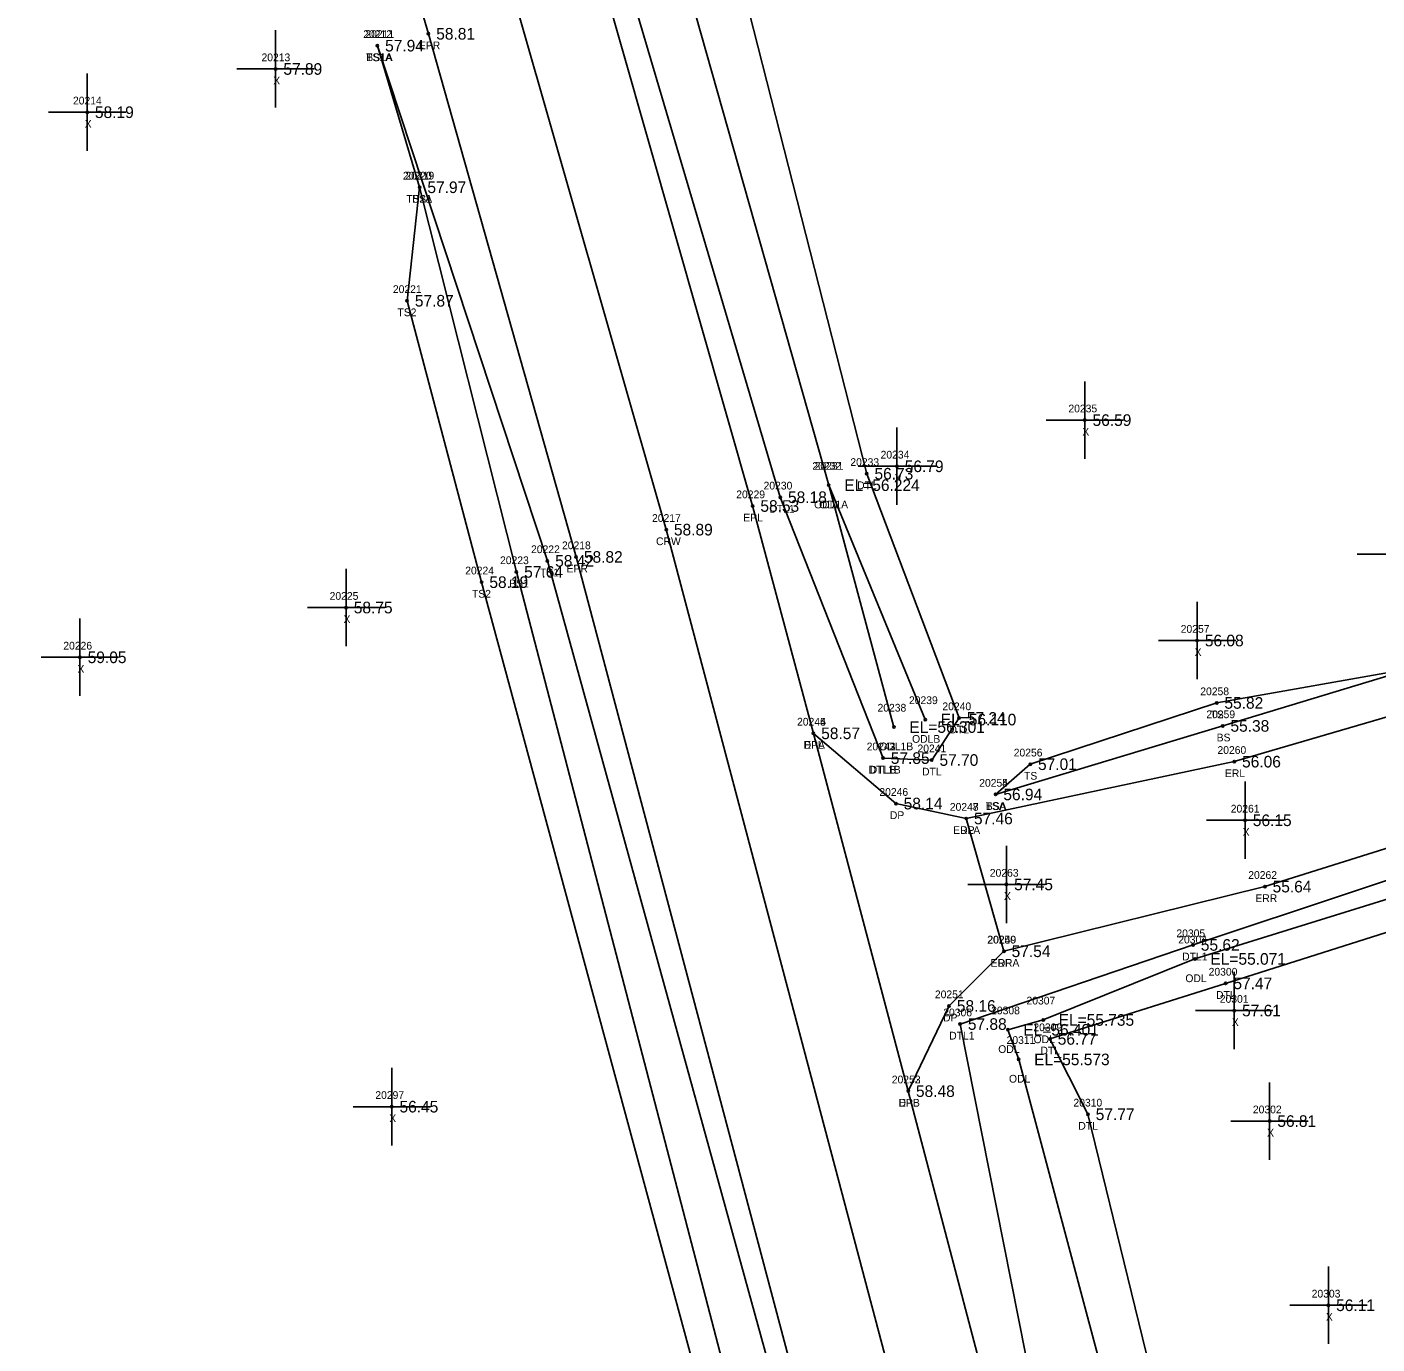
# Model space of a CAD drawing. Extents: x 2396547 to 2397655, y 770185 to 772649.
# Drawn here: x 2396876.7 to 2397051.2, y 771642.4 to 771812.6 of the extents above; entities that cross this region are included whole.
import ezdxf

# ---------------------------------------------------------------- set-up
doc = ezdxf.new("R2010")
doc.units = 0
for name, color, linetype in [('RD_DTM_BkLn1', 7, 'Continuous'), ('RD_DTM_BkLn2', 7, 'Continuous'), ('RD_DTM_BkLn_txCode', 7, 'Continuous'), ('RD_EX_Driveway', 7, 'Continuous'), ('RD_EX_Driveway_txCode', 7, 'Continuous'), ('RD_EX_H2O', 7, 'Continuous'), ('RD_EX_H2O_txCode', 7, 'Continuous'), ('RD_EX_Misc', 7, 'Continuous'), ('RD_EX_Misc_txCode', 7, 'Continuous'), ('RD_EX_Road', 7, 'Continuous'), ('RD_EX_Road_txCode', 7, 'Continuous'), ('RD_EX_TX_Driveway_ELEV', 7, 'Continuous'), ('RD_EX_TX_H2O_ELEV', 7, 'Continuous'), ('RD_EX_TX_Misc_ELEV', 7, 'Continuous'), ('RD_EX_TX_Road_ELEV', 7, 'Continuous'), ('RD_HC_Survey_ELEV', 7, 'Continuous'), ('RD_HC_Survey_txCode', 7, 'Continuous'), ('RD_SMD_Locator', 7, 'Continuous')]:
    doc.layers.add(name, color=color, linetype=linetype)

msp = doc.modelspace()

# ---------------------------------------------------------------- linework, layer by layer
at = {"layer": 'RD_DTM_BkLn1'}
msp.add_lwpolyline([(2396669.86, 772614.94), (2396704.28, 772521.49), (2396739.29, 772426.89), (2396775.36, 772328.69), (2396800.21, 772259.35), (2396825.58, 772185.8), (2396852.46, 772104.52), (2396872.48, 772041.55), (2396897.57, 771959.72), (2396918.76, 771888.68), (2396939.09, 771818.34), (2396959.29, 771747.62), (2396993.72, 771617.68), (2397022.56, 771506.67), (2397049.1, 771404.69)], dxfattribs=at)
at = {"layer": 'RD_DTM_BkLn2'}
for points in [[(2396921.95, 771810.18), (2396943.94, 771743.58), (2396982.88, 771602.26), (2397008.66, 771503.58), (2397035.9, 771402.4)], [(2396921.95, 771810.18), (2396927.42, 771791.88), (2396939.93, 771742.16), (2396976.22, 771602.97), (2396999, 771501.35), (2397026.41, 771393.39)], [(2396927.42, 771791.88), (2396925.8, 771777.21), (2396935.43, 771740.83), (2396970.29, 771612.06), (2396976.22, 771602.97)], [(2397001.88, 771713.39), (2397031.24, 771722.25), (2397055.87, 771729.7)], [(2397001.88, 771713.39), (2397006.36, 771717.3), (2397030.46, 771725.22), (2397055.87, 771729.7)]]:
    msp.add_lwpolyline(points, dxfattribs=at)
at = {"layer": 'RD_EX_Driveway'}
msp.add_lwpolyline([(2396978.33, 771721.29), (2396988.99, 771712.21), (2396998.08, 771710.28), (2397002.95, 771693.12), (2396995.87, 771686.05), (2396990.58, 771675.04)], dxfattribs=at)
at = {"layer": 'RD_EX_H2O'}
msp.add_line((2396980.31, 771753.37), (2396988.73, 771722.1), dxfattribs=at)
for points in [[(2396946.35, 771904.67), (2396938.36, 771904.07), (2396931.6, 771898.52), (2396953.06, 771822.86), (2396974.04, 771751.81), (2396987.33, 771718.09)], [(2396946.35, 771904.67), (2396967.2, 771825.55), (2396985.22, 771754.85), (2396997.16, 771723.28), (2396993.62, 771717.84), (2396987.33, 771718.09)], [(2396941.93, 771898.99), (2396960.38, 771823.86), (2396980.31, 771753.37), (2396992.79, 771723.07)], [(2397132.06, 771727.73), (2397069.65, 771707.99), (2397027.41, 771693.94), (2396997.29, 771683.71), (2397009.52, 771621.94), (2397039.8, 771510.33), (2397059.22, 771428.3), (2397068.26, 771415.82), (2397065.8, 771409.74)], [(2397133.23, 771725), (2397070.25, 771705.35), (2397027.65, 771692.13), (2397008.03, 771684.24), (2397003.46, 771682.97), (2397004.86, 771679.14), (2397019.55, 771624.25), (2397050.23, 771512.98), (2397072.95, 771431.23), (2397072.81, 771420.44), (2397072.44, 771413.81)], [(2397133.83, 771721.66), (2397071.25, 771701.52), (2397031.62, 771688.97), (2397008.91, 771681.79), (2397013.82, 771672.05), (2397025.11, 771625.88), (2397054.64, 771514.68), (2397075.97, 771429.94), (2397072.44, 771413.81)]]:
    msp.add_lwpolyline(points, dxfattribs=at)
at = {"layer": 'RD_EX_Misc'}
for p, q in [((2396908.8, 771802.17), (2396908.8, 771812.17)), ((2396884.44, 771796.58), (2396884.44, 771806.58)), ((2396903.8, 771807.17), (2396913.8, 771807.17)), ((2396879.44, 771801.58), (2396889.44, 771801.58)), ((2397013.41, 771756.78), (2397013.41, 771766.78)), ((2396989.13, 771750.81), (2396989.13, 771760.81)), ((2397008.41, 771761.78), (2397018.41, 771761.78)), ((2396984.13, 771755.81), (2396994.13, 771755.81)), ((2397048.64, 771744.47), (2397058.64, 771744.47)), ((2396917.9, 771732.55), (2396917.9, 771742.55)), ((2397027.93, 771728.29), (2397027.93, 771738.29)), ((2396883.5, 771726.12), (2396883.5, 771736.12)), ((2396912.9, 771737.55), (2396922.9, 771737.55)), ((2397022.93, 771733.29), (2397032.93, 771733.29)), ((2396878.5, 771731.12), (2396888.5, 771731.12)), ((2397034.13, 771705.05), (2397034.13, 771715.05)), ((2397029.13, 771710.05), (2397039.13, 771710.05)), ((2397003.27, 771696.76), (2397003.27, 771706.76)), ((2396998.27, 771701.76), (2397008.27, 771701.76)), ((2397032.74, 771680.46), (2397032.74, 771690.46)), ((2397027.74, 771685.46), (2397037.74, 771685.46)), ((2396923.81, 771668.03), (2396923.81, 771678.03)), ((2397037.3, 771666.17), (2397037.3, 771676.17)), ((2396918.81, 771673.03), (2396928.81, 771673.03)), ((2397032.3, 771671.17), (2397042.3, 771671.17)), ((2397044.9, 771642.36), (2397044.9, 771652.36)), ((2397039.9, 771647.36), (2397049.9, 771647.36))]:
    msp.add_line(p, q, dxfattribs=at)
at = {"layer": 'RD_EX_Road'}
for points in [[(2396680.92, 772617.84), (2396715.6, 772525.73), (2396750.68, 772430.62), (2396786.3, 772332.21), (2396811.38, 772263.31), (2396839.69, 772181.74), (2396863.75, 772109.83), (2396883.63, 772046.56), (2396889.54, 772027.11), (2396896.25, 772004.37), (2396904.34, 771978.33), (2396908.24, 771964.89), (2396921.74, 771919.68), (2396927.03, 771902.11), (2396950.2, 771821.74), (2396970.47, 771750.68), (2396978.33, 771721.29), (2396990.58, 771675.04), (2397004.94, 771620.49), (2397034.26, 771508.8), (2397061.11, 771410.49), (2397060.64, 771407.04), (2397062.07, 771407.67)], [(2396658.78, 772611.07), (2396693.37, 772516.9), (2396729.65, 772418.78), (2396760.7, 772333.11), (2396788.58, 772254.87), (2396814.65, 772181.57), (2396841.1, 772100.86), (2396861.19, 772037.76), (2396886.09, 771955.71), (2396907.15, 771884.49), (2396928.56, 771811.72), (2396947.65, 771744.09), (2396985.17, 771602.64), (2397011.11, 771504.04), (2397037.95, 771404.25), (2397039, 771401.22)], [(2396998.08, 771710.28), (2397032.74, 771717.63), (2397062.52, 771726.35), (2397126.64, 771745.15)], [(2397002.95, 771693.12), (2397036.69, 771701.48), (2397068.39, 771711.44), (2397131.44, 771730.05)]]:
    msp.add_lwpolyline(points, dxfattribs=at)
at = {"layer": 'RD_SMD_Locator'}
for centre in [(2396928.56, 771811.72), (2396921.95, 771810.18), (2396921.95, 771810.18), (2396908.8, 771807.17), (2396884.44, 771801.58), (2396927.42, 771791.88), (2396927.42, 771791.88), (2396925.8, 771777.21), (2397013.41, 771761.78), (2396989.13, 771755.81), (2396980.31, 771753.37), (2396980.31, 771753.37), (2396985.22, 771754.85), (2396974.04, 771751.81), (2396970.47, 771750.68), (2396959.29, 771747.62), (2396943.94, 771743.58), (2396947.65, 771744.09), (2396939.93, 771742.16), (2396935.43, 771740.83), (2396917.9, 771737.55), (2397027.93, 771733.29), (2396883.5, 771731.12), (2397030.46, 771725.22), (2396988.73, 771722.1), (2396992.79, 771723.07), (2396997.16, 771723.28), (2397031.24, 771722.25), (2396978.33, 771721.29), (2396978.33, 771721.29), (2396987.33, 771718.09), (2396987.33, 771718.09), (2396993.62, 771717.84), (2397006.36, 771717.3), (2397032.74, 771717.63), (2397001.88, 771713.39), (2397001.88, 771713.39), (2396988.99, 771712.21), (2396998.08, 771710.28), (2396998.08, 771710.28), (2397034.13, 771710.05), (2397003.27, 771701.76), (2397036.69, 771701.48), (2397002.95, 771693.12), (2397002.95, 771693.12), (2397027.41, 771693.94), (2397027.65, 771692.13), (2397031.62, 771688.97), (2396995.87, 771686.05), (2397032.74, 771685.46), (2396997.29, 771683.71), (2397008.03, 771684.24), (2397003.46, 771682.97), (2397008.91, 771681.79), (2397004.86, 771679.14), (2396990.58, 771675.04), (2396990.58, 771675.04), (2396923.81, 771673.03), (2397013.82, 771672.05), (2397037.3, 771671.17), (2397044.9, 771647.36)]:
    msp.add_circle(centre, 0.15, dxfattribs=at)

# ---------------------------------------------------------------- texts
at = {"layer": 'RD_DTM_BkLn_txCode'}
for s, p in [('20212', (2396920.12, 771811.18)), ('20211', (2396920.4, 771811.18)), ('TS1A', (2396920.5, 771808.18)), ('BS1A', (2396920.52, 771808.18)), ('20220', (2396925.26, 771792.88)), ('20219', (2396925.58, 771792.88)), ('TS2A', (2396925.69, 771789.88)), ('BS1', (2396926.47, 771789.88)), ('20221', (2396923.96, 771778.21)), ('TS2', (2396924.55, 771775.21)), ('20222', (2396941.82, 771744.58)), ('20223', (2396937.81, 771743.16)), ('20224', (2396933.31, 771741.83)), ('TS1', (2396942.98, 771741.58)), ('TS2', (2396934.18, 771738.83)), ('BS1', (2396938.99, 771740.16)), ('20258', (2397028.34, 771726.22)), ('20259', (2397029.12, 771723.25)), ('TS', (2397029.66, 771723.22)), ('BS', (2397030.46, 771720.25)), ('20256', (2397004.22, 771718.3)), ('20254', (2396999.76, 771714.39)), ('20255', (2396999.76, 771714.39)), ('TS', (2397005.56, 771715.3)), ('TSA', (2397000.59, 771711.39)), ('BSA', (2397000.61, 771711.39))]:
    msp.add_text(s, height=1, dxfattribs=at).set_placement(p)
at = {"layer": 'RD_EX_Driveway_txCode'}
for s, p in [('20245', (2396976.21, 771722.29)), ('DPA', (2396977.06, 771719.29)), ('20246', (2396986.85, 771713.21)), ('20247', (2396995.96, 771711.28)), ('DP', (2396988.21, 771710.21)), ('DP', (2396997.3, 771708.28)), ('20249', (2397000.83, 771694.12)), ('DP', (2397002.17, 771691.12)), ('20251', (2396994.03, 771687.05)), ('DP', (2396995.09, 771684.05)), ('20252', (2396988.46, 771676.04)), ('DPB', (2396989.33, 771673.04))]:
    msp.add_text(s, height=1, dxfattribs=at).set_placement(p)
at = {"layer": 'RD_EX_H2O_txCode'}
for s, p in [('20232', (2396978.19, 771755.37)), ('20231', (2396978.48, 771755.37)), ('20233', (2396983.1, 771755.85)), ('20230', (2396971.88, 771752.81)), ('DTL', (2396983.98, 771752.85)), ('DTL1', (2396972.63, 771749.81)), ('ODL1A', (2396978.42, 771750.37)), ('ODL', (2396979.07, 771750.37)), ('20239', (2396990.68, 771725.07)), ('20238', (2396986.61, 771724.1)), ('20240', (2396995, 771724.28)), ('DTL', (2396995.91, 771721.28)), ('ODLB', (2396991.08, 771720.07)), ('20242', (2396985.21, 771719.09)), ('20243', (2396985.21, 771719.09)), ('ODL1B', (2396986.84, 771719.1)), ('20241', (2396991.78, 771718.84)), ('DTL1B', (2396985.45, 771716.09)), ('DTLB', (2396985.61, 771716.09)), ('DTL', (2396992.37, 771715.84)), ('20305', (2397025.25, 771694.94)), ('20304', (2397025.49, 771694.13)), ('DTL1', (2397026, 771691.94)), ('20300', (2397029.42, 771689.97)), ('ODL', (2397026.41, 771689.13)), ('20307', (2397005.87, 771686.24)), ('DTL', (2397030.38, 771686.97)), ('20306', (2396995.11, 771684.71)), ('20308', (2397001.3, 771684.97)), ('20309', (2397006.76, 771682.79)), ('DTL1', (2396995.88, 771681.71)), ('20311', (2397003.3, 771681.14)), ('ODL', (2397006.79, 771681.24)), ('ODL', (2397002.22, 771679.97)), ('DTL', (2397007.67, 771679.79)), ('ODL', (2397003.61, 771676.14)), ('20310', (2397011.94, 771673.05)), ('DTL', (2397012.57, 771670.05))]:
    msp.add_text(s, height=1, dxfattribs=at).set_placement(p)
at = {"layer": 'RD_EX_Misc_txCode'}
for s, p in [('20213', (2396906.97, 771808.17)), ('X', (2396908.49, 771805.17)), ('20214', (2396882.6, 771802.58)), ('X', (2396884.12, 771799.58)), ('20235', (2397011.29, 771762.78)), ('X', (2397013.09, 771759.78)), ('20234', (2396987.01, 771756.81)), ('X', (2396988.81, 771753.81)), ('20225', (2396915.78, 771738.55)), ('X', (2396917.58, 771735.55)), ('20257', (2397025.81, 771734.29)), ('20226', (2396881.35, 771732.12)), ('X', (2397027.61, 771731.29)), ('X', (2396883.18, 771729.12)), ('20261', (2397032.28, 771711.05)), ('X', (2397033.82, 771708.05)), ('20263', (2397001.13, 771702.76)), ('X', (2397002.96, 771699.76)), ('20301', (2397030.86, 771686.46)), ('X', (2397032.42, 771683.46)), ('20297', (2396921.69, 771674.03)), ('X', (2396923.49, 771671.03)), ('20302', (2397035.14, 771672.17)), ('X', (2397036.98, 771669.17)), ('20303', (2397042.74, 771648.36)), ('X', (2397044.58, 771645.36))]:
    msp.add_text(s, height=1, dxfattribs=at).set_placement(p)
at = {"layer": 'RD_EX_Road_txCode'}
for s, p in [('EPR', (2396927.33, 771809.72)), ('20229', (2396968.35, 771751.68)), ('EPL', (2396969.26, 771748.68)), ('20218', (2396945.82, 771745.09)), ('EPR', (2396946.42, 771742.09)), ('20244', (2396976.21, 771722.29)), ('EPL', (2396977.13, 771719.29)), ('20260', (2397030.56, 771718.63)), ('ERL', (2397031.53, 771715.63)), ('20248', (2396995.96, 771711.28)), ('ERLA', (2396996.39, 771708.28)), ('20262', (2397034.54, 771702.48)), ('ERR', (2397035.46, 771699.48)), ('20250', (2397000.79, 771694.12)), ('ERRA', (2397001.23, 771691.12)), ('20253', (2396988.46, 771676.04)), ('EPL', (2396989.38, 771673.04))]:
    msp.add_text(s, height=1, dxfattribs=at).set_placement(p)
at = {"layer": 'RD_EX_TX_Driveway_ELEV'}
for s, p in [('58.57', (2396979.33, 771720.54)), ('58.14', (2396989.99, 771711.46)), ('57.46', (2396999.08, 771709.53)), ('57.54', (2397003.95, 771692.37)), ('58.16', (2396996.87, 771685.3)), ('58.48', (2396991.58, 771674.29))]:
    msp.add_text(s, height=1.5, dxfattribs=at).set_placement(p)
at = {"layer": 'RD_EX_TX_H2O_ELEV'}
for s, p in [('56.73', (2396986.22, 771754.1)), ('EL=56.224', (2396982.31, 771752.62)), ('EL=56.224', (2396982.31, 771752.62)), ('58.18', (2396975.04, 771751.06)), ('57.24', (2396998.16, 771722.53)), ('EL=56.301', (2396990.73, 771721.35)), ('EL=56.110', (2396994.79, 771722.32)), ('57.85', (2396988.33, 771717.34)), ('57.85', (2396988.33, 771717.34)), ('57.70', (2396994.62, 771717.09)), ('55.62', (2397028.41, 771693.19)), ('EL=55.071', (2397029.65, 771691.38)), ('57.47', (2397032.62, 771688.22)), ('57.88', (2396998.29, 771682.96)), ('EL=56.401', (2397005.46, 771682.22)), ('EL=55.735', (2397010.03, 771683.49)), ('56.77', (2397009.91, 771681.04)), ('EL=55.573', (2397006.86, 771678.39)), ('57.77', (2397014.82, 771671.3))]:
    msp.add_text(s, height=1.5, dxfattribs=at).set_placement(p)
at = {"layer": 'RD_EX_TX_Misc_ELEV'}
for s, p in [('57.94', (2396922.95, 771809.43)), ('57.94', (2396922.95, 771809.43)), ('57.89', (2396909.8, 771806.42)), ('58.19', (2396885.44, 771800.83)), ('57.97', (2396928.42, 771791.13)), ('57.97', (2396928.42, 771791.13)), ('57.87', (2396926.8, 771776.46)), ('56.59', (2397014.41, 771761.03)), ('56.79', (2396990.13, 771755.06)), ('58.42', (2396944.94, 771742.83)), ('58.19', (2396936.43, 771740.08)), ('57.64', (2396940.93, 771741.41)), ('58.75', (2396918.9, 771736.8)), ('56.08', (2397028.93, 771732.54)), ('59.05', (2396884.5, 771730.37)), ('55.82', (2397031.46, 771724.47)), ('55.38', (2397032.24, 771721.5)), ('57.01', (2397007.36, 771716.55)), ('56.94', (2397002.88, 771712.64)), ('56.94', (2397002.88, 771712.64)), ('56.15', (2397035.13, 771709.3)), ('57.45', (2397004.27, 771701.01)), ('57.61', (2397033.74, 771684.71)), ('56.45', (2396924.81, 771672.28)), ('56.81', (2397038.3, 771670.42)), ('56.11', (2397045.9, 771646.61))]:
    msp.add_text(s, height=1.5, dxfattribs=at).set_placement(p)
at = {"layer": 'RD_EX_TX_Road_ELEV'}
for s, p in [('58.81', (2396929.56, 771810.97)), ('58.53', (2396971.47, 771749.93)), ('58.82', (2396948.65, 771743.34)), ('58.57', (2396979.33, 771720.54)), ('56.06', (2397033.74, 771716.88)), ('57.46', (2396999.08, 771709.53)), ('55.64', (2397037.69, 771700.73)), ('57.54', (2397003.95, 771692.37)), ('58.48', (2396991.58, 771674.29))]:
    msp.add_text(s, height=1.5, dxfattribs=at).set_placement(p)
at = {"layer": 'RD_HC_Survey_ELEV'}
msp.add_text('58.89', height=1.5, dxfattribs=at).set_placement((2396960.29, 771746.87))
at = {"layer": 'RD_HC_Survey_txCode'}
for s, p in [('20217', (2396957.46, 771748.62)), ('CRW', (2396957.98, 771745.62))]:
    msp.add_text(s, height=1, dxfattribs=at).set_placement(p)

doc.saveas('drawing.dxf')
